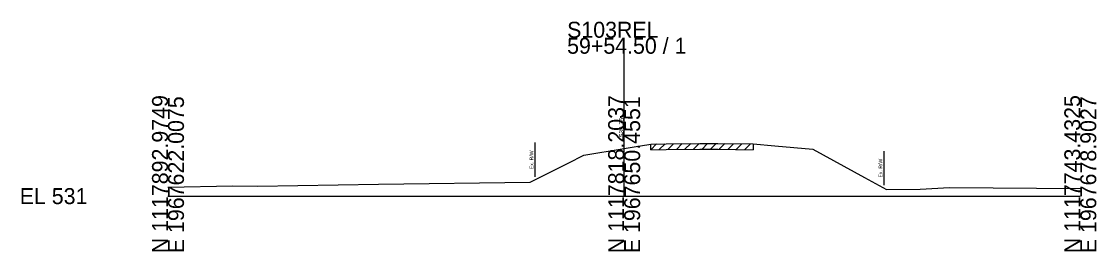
# Model space of a CAD drawing. Extents: x -26 to 163, y -10 to 24518.
# Drawn here: x -25.7 to 162.8, y 10990.3 to 11030.6 of the extents above; entities that cross this region are included whole.
import ezdxf

# ---------------------------------------------------------------- set-up
doc = ezdxf.new("R2010")
doc.units = 0
for name, color, linetype in [('RD_GPK_XS_Cell', 7, 'Continuous'), ('RD_XS_ExGround', 7, 'Continuous'), ('RD_XS_ExPaveRet', 7, 'Continuous'), ('RD_XS_ExRW', 7, 'Continuous'), ('RD_XS_TX_Elev_EX', 7, 'Continuous')]:
    doc.layers.add(name, color=color, linetype=linetype)

msp = doc.modelspace()

# ---------------------------------------------------------------- linework, layer by layer
at = {"layer": 'RD_GPK_XS_Cell'}
for p, q in [((80, 11000), (80, 11027.73)), ((0, 11000), (80, 11000)), ((80, 11000), (160, 11000))]:
    msp.add_line(p, q, dxfattribs=at)
at = {"layer": 'RD_XS_ExGround'}
msp.add_lwpolyline([(0, 11001.55), (11.35, 11001.8), (15.7, 11001.76), (36.91, 11002.12), (63.54, 11002.47), (70.17, 11005.79), (72.95, 11007.17), (80, 11008.35), (81.39, 11008.59), (84.66, 11009.12), (87.38, 11009.16), (93.26, 11009.24), (96.41, 11009.2), (102.6, 11009.13), (106.4, 11008.78), (113.08, 11008.23), (122.18, 11003.24), (126.03, 11001.13), (131.94, 11001.24), (137.05, 11001.49), (160, 11001.36)], dxfattribs=at)
at = {"layer": 'RD_XS_ExPaveRet'}
for p, q in [((84.66, 11008.12), (85.67, 11009.13)), ((84.66, 11008.12), (84.66, 11009.12)), ((86.16, 11008.14), (87.17, 11009.15)), ((87.66, 11008.16), (88.67, 11009.18)), ((89.16, 11008.18), (90.17, 11009.2)), ((90.66, 11008.21), (91.67, 11009.22)), ((92.16, 11008.23), (93.17, 11009.24)), ((93.66, 11008.24), (94.64, 11009.22)), ((95.16, 11008.22), (96.14, 11009.2)), ((96.66, 11008.2), (97.65, 11009.19)), ((98.16, 11008.18), (99.15, 11009.17)), ((99.66, 11008.17), (100.65, 11009.15)), ((101.16, 11008.15), (102.15, 11009.14)), ((102.6, 11009.13), (102.6, 11008.13)), ((84.66, 11008.12), (87.38, 11008.16)), ((87.38, 11008.16), (93.26, 11008.24)), ((93.26, 11008.24), (96.41, 11008.2)), ((96.41, 11008.2), (102.6, 11008.13))]:
    msp.add_line(p, q, dxfattribs=at)
at = {"layer": 'RD_XS_ExRW'}
for p, q in [((64.33, 11009.37), (64.33, 11003.37)), ((125.54, 11007.9), (125.54, 11001.9))]:
    msp.add_line(p, q, dxfattribs=at)

# ---------------------------------------------------------------- texts
at = {"layer": 'RD_GPK_XS_Cell'}
for s, p in [('S103REL', (70, 11027.73)), ('59+54.50 / 1', (70, 11024.93)), ('EL 531', (-26, 10998.6))]:
    msp.add_text(s, height=2.8, dxfattribs=at).set_placement(p)
for s, p in [('N 1117892.9749', (0, 10990)), ('E 1967622.0075', (2.8, 10990)), ('N 1117818.2037', (80, 10990)), ('E 1967650.4551', (82.8, 10990)), ('N 1117743.4325', (160, 10990)), ('E 1967678.9027', (162.8, 10990))]:
    msp.add_text(s, height=2.8, rotation=90, dxfattribs=at).set_placement(p)
at = {"layer": 'RD_XS_ExRW'}
for p in [(64.08, 11004.71), (125.29, 11003.25)]:
    msp.add_text('Ex. R/W ', height=0.65, rotation=90, dxfattribs=at).set_placement(p)
at = {"layer": 'RD_XS_TX_Elev_EX'}
msp.add_text('539.35', height=0.8, rotation=90, dxfattribs=at).set_placement((79.9, 11010.35))

doc.saveas('drawing.dxf')
